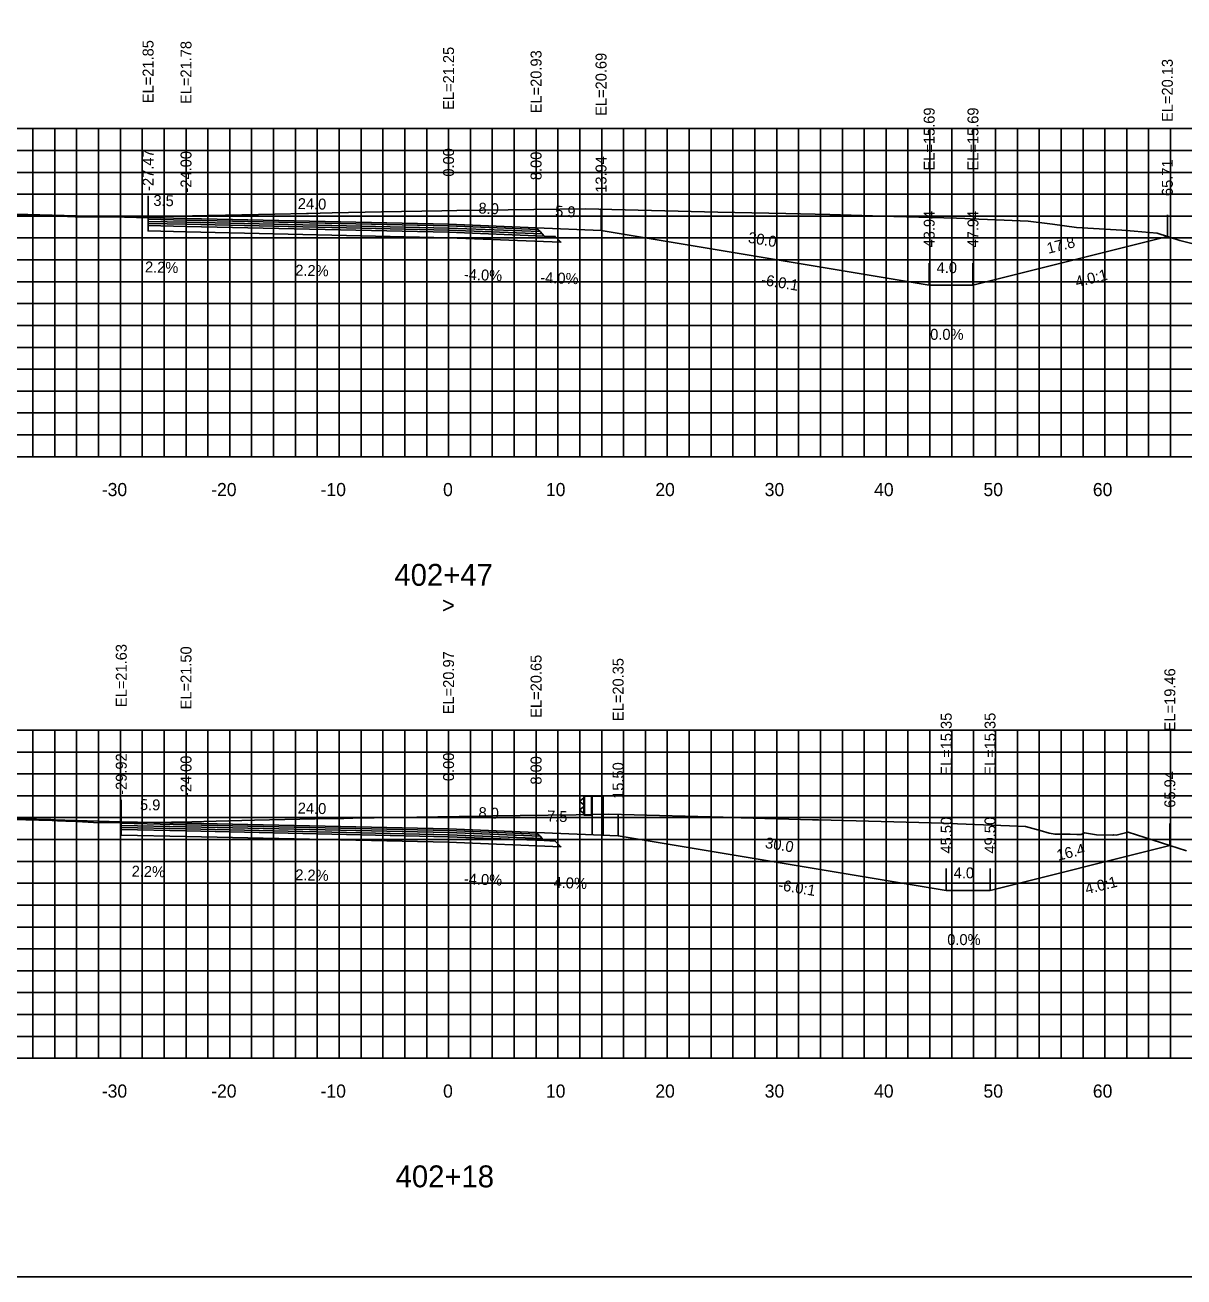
# Model space of a CAD drawing. Extents: x 1800976 to 1805104, y 250057 to 250580.
# Drawn here: x 1802252.3 to 1802358.2, y 250079.4 to 250193.9 of the extents above; entities that cross this region are included whole.
import ezdxf

# ---------------------------------------------------------------- set-up
doc = ezdxf.new("R2010")
doc.units = 0
for name, color, linetype in [('1', 7, 'Continuous'), ('10', 7, 'Continuous'), ('3', 7, 'Continuous'), ('4', 7, 'Continuous'), ('60', 7, 'Continuous'), ('BASE', 7, 'Continuous'), ('CL-CNST', 7, 'Continuous'), ('Level 1', 7, 'Continuous'), ('Level 62', 7, 'Continuous'), ('LOWER BINDER', 7, 'Continuous'), ('M-ROADS', 7, 'Continuous'), ('UPPER BINDER', 7, 'Continuous'), ('WEARING', 7, 'Continuous')]:
    doc.layers.add(name, color=color, linetype=linetype)

msp = doc.modelspace()

# ---------------------------------------------------------------- linework, layer by layer
for p, q in [((1802263.53, 250176.29), (1802263.53, 250178.29)), ((1802267, 250176.21), (1802267, 250178.21)), ((1802291, 250175.68), (1802291, 250177.68)), ((1802299, 250175.36), (1802299, 250177.36)), ((1802304.94, 250175.12), (1802304.94, 250177.12)), ((1802356.71, 250174.56), (1802356.71, 250176.56)), ((1802334.94, 250170.12), (1802334.94, 250172.12)), ((1802338.94, 250170.12), (1802338.94, 250172.12)), ((1802261.08, 250121.06), (1802261.08, 250123.06)), ((1802267, 250120.93), (1802267, 250122.93)), ((1802291, 250120.4), (1802291, 250122.4)), ((1802299, 250120.08), (1802299, 250122.08)), ((1802306.5, 250119.78), (1802306.5, 250121.78)), ((1802356.94, 250118.89), (1802356.94, 250120.89)), ((1802336.5, 250114.78), (1802336.5, 250116.78)), ((1802340.5, 250114.78), (1802340.5, 250116.78))]:
    msp.add_line(p, q)
msp.add_lwpolyline([(1802141, 250079.43), (1802441, 250079.43), (1802441, 250269.43), (1802141, 250269.43)], close=True)
at = {"layer": '60'}
for p, q in [((1802141, 250154.43), (1802441, 250154.43)), ((1802261, 250154.37), (1802261, 250154.43)), ((1802271, 250154.37), (1802271, 250154.43)), ((1802281, 250154.37), (1802281, 250154.43)), ((1802291, 250154.37), (1802291, 250154.43)), ((1802301, 250154.37), (1802301, 250154.43)), ((1802311, 250154.37), (1802311, 250154.43)), ((1802321, 250154.37), (1802321, 250154.43)), ((1802331, 250154.37), (1802331, 250154.43)), ((1802341, 250154.37), (1802341, 250154.43)), ((1802351, 250154.37), (1802351, 250154.43)), ((1802141, 250099.43), (1802441, 250099.43)), ((1802261, 250099.37), (1802261, 250099.43)), ((1802271, 250099.37), (1802271, 250099.43)), ((1802281, 250099.37), (1802281, 250099.43)), ((1802291, 250099.37), (1802291, 250099.43)), ((1802301, 250099.37), (1802301, 250099.43)), ((1802311, 250099.37), (1802311, 250099.43)), ((1802321, 250099.37), (1802321, 250099.43)), ((1802331, 250099.37), (1802331, 250099.43)), ((1802341, 250099.37), (1802341, 250099.43)), ((1802351, 250099.37), (1802351, 250099.43))]:
    msp.add_line(p, q, dxfattribs=at)
at = {"layer": 'BASE'}
for points in [[(1802263.53, 250175.57), (1802267, 250175.49), (1802291, 250174.96), (1802299.75, 250174.61), (1802300.75, 250174.57), (1802301.27, 250174.05), (1802291, 250174.46), (1802267, 250174.99), (1802263.53, 250175.07)], [(1802261.08, 250120.34), (1802267, 250120.21), (1802291, 250119.68), (1802299.75, 250119.33), (1802300.75, 250119.29), (1802301.27, 250118.77), (1802291, 250119.18), (1802267, 250119.71), (1802261.08, 250119.84)]]:
    msp.add_lwpolyline(points, close=True, dxfattribs=at)
at = {"layer": 'CL-CNST'}
for points in [[(1802251.44, 250176.61), (1802261.38, 250176.32), (1802263.53, 250176.27), (1802263.53, 250176.25)], [(1802263.53, 250176.29), (1802267, 250176.21), (1802291, 250175.68), (1802299, 250175.36), (1802304.94, 250175.12), (1802334.94, 250170.12), (1802338.94, 250170.12), (1802356.71, 250174.56)], [(1802242.86, 250121.52), (1802254.65, 250121.25), (1802254.93, 250121.24), (1802259.97, 250121.09), (1802261, 250121.06)], [(1802261.08, 250121.06), (1802267, 250120.93), (1802291, 250120.4), (1802299, 250120.08), (1802306.5, 250119.78), (1802336.5, 250114.78), (1802340.5, 250114.78), (1802356.94, 250118.89)]]:
    msp.add_lwpolyline(points, dxfattribs=at)
at = {"layer": 'Level 1'}
for p, q in [((1802303.38, 250123.25), (1802303.02, 250122.96)), ((1802303.38, 250123.4), (1802303.38, 250121.65)), ((1802305.13, 250123.4), (1802303.38, 250123.4)), ((1802303.43, 250123.4), (1802303.43, 250121.65)), ((1802304.08, 250123.4), (1802304.08, 250121.65)), ((1802304.13, 250123.4), (1802304.13, 250119.88)), ((1802305.13, 250123.4), (1802305.13, 250119.84)), ((1802303.02, 250122.88), (1802303.38, 250122.6)), ((1802303.38, 250122.46), (1802303.02, 250122.16)), ((1802303.02, 250122.09), (1802303.38, 250121.8)), ((1802304.13, 250121.65), (1802303.38, 250121.65))]:
    msp.add_line(p, q, dxfattribs=at)
for centre in [(1802303.05, 250122.92), (1802303.05, 250122.13)]:
    msp.add_arc(centre, 0.05, 135, 226.6208, dxfattribs=at)
at = {"layer": 'Level 62'}
for p, q in [((1802141, 250184.43), (1802441, 250184.43)), ((1802253, 250154.43), (1802253, 250184.43)), ((1802255, 250154.43), (1802255, 250184.43)), ((1802257, 250154.43), (1802257, 250184.43)), ((1802259, 250154.43), (1802259, 250184.43)), ((1802261, 250154.43), (1802261, 250184.43)), ((1802263, 250154.43), (1802263, 250184.43)), ((1802265, 250154.43), (1802265, 250184.43)), ((1802267, 250154.43), (1802267, 250184.43)), ((1802269, 250154.43), (1802269, 250184.43)), ((1802271, 250154.43), (1802271, 250184.43)), ((1802273, 250154.43), (1802273, 250184.43)), ((1802275, 250154.43), (1802275, 250184.43)), ((1802277, 250154.43), (1802277, 250184.43)), ((1802279, 250154.43), (1802279, 250184.43)), ((1802281, 250154.43), (1802281, 250184.43)), ((1802283, 250154.43), (1802283, 250184.43)), ((1802285, 250154.43), (1802285, 250184.43)), ((1802287, 250154.43), (1802287, 250184.43)), ((1802289, 250154.43), (1802289, 250184.43)), ((1802291, 250154.43), (1802291, 250184.43)), ((1802293, 250154.43), (1802293, 250184.43)), ((1802295, 250154.43), (1802295, 250184.43)), ((1802297, 250154.43), (1802297, 250184.43)), ((1802299, 250154.43), (1802299, 250184.43)), ((1802301, 250154.43), (1802301, 250184.43)), ((1802303, 250154.43), (1802303, 250184.43)), ((1802305, 250154.43), (1802305, 250184.43)), ((1802307, 250154.43), (1802307, 250184.43)), ((1802309, 250154.43), (1802309, 250184.43)), ((1802311, 250154.43), (1802311, 250184.43)), ((1802313, 250154.43), (1802313, 250184.43)), ((1802315, 250154.43), (1802315, 250184.43)), ((1802317, 250154.43), (1802317, 250184.43)), ((1802319, 250154.43), (1802319, 250184.43)), ((1802321, 250154.43), (1802321, 250184.43)), ((1802323, 250154.43), (1802323, 250184.43)), ((1802325, 250154.43), (1802325, 250184.43)), ((1802327, 250154.43), (1802327, 250184.43)), ((1802329, 250154.43), (1802329, 250184.43)), ((1802331, 250154.43), (1802331, 250184.43)), ((1802333, 250154.43), (1802333, 250184.43)), ((1802335, 250154.43), (1802335, 250184.43)), ((1802337, 250154.43), (1802337, 250184.43)), ((1802339, 250154.43), (1802339, 250184.43)), ((1802341, 250154.43), (1802341, 250184.43)), ((1802343, 250154.43), (1802343, 250184.43)), ((1802345, 250154.43), (1802345, 250184.43)), ((1802347, 250154.43), (1802347, 250184.43)), ((1802349, 250154.43), (1802349, 250184.43)), ((1802351, 250154.43), (1802351, 250184.43)), ((1802353, 250154.43), (1802353, 250184.43)), ((1802355, 250154.43), (1802355, 250184.43)), ((1802357, 250154.43), (1802357, 250184.43)), ((1802141, 250182.43), (1802441, 250182.43)), ((1802141, 250180.43), (1802441, 250180.43)), ((1802141, 250178.43), (1802441, 250178.43)), ((1802141, 250176.43), (1802441, 250176.43)), ((1802141, 250174.43), (1802441, 250174.43)), ((1802141, 250172.43), (1802441, 250172.43)), ((1802141, 250170.43), (1802441, 250170.43)), ((1802141, 250168.43), (1802441, 250168.43)), ((1802141, 250166.43), (1802441, 250166.43)), ((1802141, 250164.43), (1802441, 250164.43)), ((1802141, 250162.43), (1802441, 250162.43)), ((1802141, 250160.43), (1802441, 250160.43)), ((1802141, 250158.43), (1802441, 250158.43)), ((1802141, 250156.43), (1802441, 250156.43)), ((1802141, 250154.43), (1802441, 250154.43)), ((1802141, 250129.43), (1802441, 250129.43)), ((1802253, 250099.43), (1802253, 250129.43)), ((1802255, 250099.43), (1802255, 250129.43)), ((1802257, 250099.43), (1802257, 250129.43)), ((1802259, 250099.43), (1802259, 250129.43)), ((1802261, 250099.43), (1802261, 250129.43)), ((1802263, 250099.43), (1802263, 250129.43)), ((1802265, 250099.43), (1802265, 250129.43)), ((1802267, 250099.43), (1802267, 250129.43)), ((1802269, 250099.43), (1802269, 250129.43)), ((1802271, 250099.43), (1802271, 250129.43)), ((1802273, 250099.43), (1802273, 250129.43)), ((1802275, 250099.43), (1802275, 250129.43)), ((1802277, 250099.43), (1802277, 250129.43)), ((1802279, 250099.43), (1802279, 250129.43)), ((1802281, 250099.43), (1802281, 250129.43)), ((1802283, 250099.43), (1802283, 250129.43)), ((1802285, 250099.43), (1802285, 250129.43)), ((1802287, 250099.43), (1802287, 250129.43)), ((1802289, 250099.43), (1802289, 250129.43)), ((1802291, 250099.43), (1802291, 250129.43)), ((1802293, 250099.43), (1802293, 250129.43)), ((1802295, 250099.43), (1802295, 250129.43)), ((1802297, 250099.43), (1802297, 250129.43)), ((1802299, 250099.43), (1802299, 250129.43)), ((1802301, 250099.43), (1802301, 250129.43)), ((1802303, 250099.43), (1802303, 250129.43)), ((1802305, 250099.43), (1802305, 250129.43)), ((1802307, 250099.43), (1802307, 250129.43)), ((1802309, 250099.43), (1802309, 250129.43)), ((1802311, 250099.43), (1802311, 250129.43)), ((1802313, 250099.43), (1802313, 250129.43)), ((1802315, 250099.43), (1802315, 250129.43)), ((1802317, 250099.43), (1802317, 250129.43)), ((1802319, 250099.43), (1802319, 250129.43)), ((1802321, 250099.43), (1802321, 250129.43)), ((1802323, 250099.43), (1802323, 250129.43)), ((1802325, 250099.43), (1802325, 250129.43)), ((1802327, 250099.43), (1802327, 250129.43)), ((1802329, 250099.43), (1802329, 250129.43)), ((1802331, 250099.43), (1802331, 250129.43)), ((1802333, 250099.43), (1802333, 250129.43)), ((1802335, 250099.43), (1802335, 250129.43)), ((1802337, 250099.43), (1802337, 250129.43)), ((1802339, 250099.43), (1802339, 250129.43)), ((1802341, 250099.43), (1802341, 250129.43)), ((1802343, 250099.43), (1802343, 250129.43)), ((1802345, 250099.43), (1802345, 250129.43)), ((1802347, 250099.43), (1802347, 250129.43)), ((1802349, 250099.43), (1802349, 250129.43)), ((1802351, 250099.43), (1802351, 250129.43)), ((1802353, 250099.43), (1802353, 250129.43)), ((1802355, 250099.43), (1802355, 250129.43)), ((1802357, 250099.43), (1802357, 250129.43)), ((1802141, 250127.43), (1802441, 250127.43)), ((1802141, 250125.43), (1802441, 250125.43)), ((1802141, 250123.43), (1802441, 250123.43)), ((1802141, 250121.43), (1802441, 250121.43)), ((1802141, 250119.43), (1802441, 250119.43)), ((1802141, 250117.43), (1802441, 250117.43)), ((1802141, 250115.43), (1802441, 250115.43)), ((1802141, 250113.43), (1802441, 250113.43)), ((1802141, 250111.43), (1802441, 250111.43)), ((1802141, 250109.43), (1802441, 250109.43)), ((1802141, 250107.43), (1802441, 250107.43)), ((1802141, 250105.43), (1802441, 250105.43)), ((1802141, 250103.43), (1802441, 250103.43)), ((1802141, 250101.43), (1802441, 250101.43)), ((1802141, 250099.43), (1802441, 250099.43))]:
    msp.add_line(p, q, dxfattribs=at)
at = {"layer": 'LOWER BINDER'}
for points in [[(1802267, 250175.87), (1802291, 250175.34), (1802299.36, 250175.01), (1802299.55, 250174.81), (1802291, 250175.15), (1802267, 250175.68), (1802263.53, 250175.76), (1802263.53, 250175.95)], [(1802267, 250175.68), (1802291, 250175.15), (1802299.55, 250174.81), (1802299.75, 250174.61), (1802291, 250174.96), (1802267, 250175.49), (1802263.53, 250175.57), (1802263.53, 250175.76)], [(1802267, 250120.59), (1802291, 250120.06), (1802299.36, 250119.73), (1802299.55, 250119.53), (1802291, 250119.87), (1802267, 250120.4), (1802261.08, 250120.53), (1802261.08, 250120.72)], [(1802267, 250120.4), (1802291, 250119.87), (1802299.55, 250119.53), (1802299.75, 250119.33), (1802291, 250119.68), (1802267, 250120.21), (1802261.08, 250120.34), (1802261.08, 250120.53)]]:
    msp.add_lwpolyline(points, close=True, dxfattribs=at)
at = {"layer": 'M-ROADS'}
for points in [[(1802249.64, 250176.61), (1802252.58, 250176.54), (1802253.34, 250176.51), (1802253.83, 250176.49), (1802255.43, 250176.42), (1802256.86, 250176.36), (1802262.14, 250176.36), (1802263.94, 250176.37), (1802265.04, 250176.4), (1802267.58, 250176.47), (1802275.13, 250176.62), (1802278.01, 250176.68), (1802278.2, 250176.68), (1802279.26, 250176.71), (1802280.37, 250176.73), (1802284.88, 250176.81), (1802290.39, 250176.92), (1802291.75, 250176.95), (1802298.79, 250177.03), (1802303.53, 250177.1), (1802309.54, 250176.94), (1802315.62, 250176.79), (1802321.84, 250176.67), (1802325.85, 250176.59), (1802331.71, 250176.41), (1802337.43, 250176.24), (1802338.19, 250176.2), (1802338.68, 250176.18), (1802341.07, 250176.08), (1802343.98, 250175.97), (1802346.2, 250175.69), (1802348.4, 250175.4), (1802352.55, 250175.16), (1802353.67, 250175.05), (1802355.77, 250174.86), (1802357.86, 250174.2), (1802360.54, 250173.53)], [(1802249.89, 250121.29), (1802254.76, 250121.17), (1802255.26, 250121.15), (1802256.01, 250121.12), (1802257.05, 250121.07), (1802259.03, 250120.97), (1802265.68, 250121.01), (1802266.11, 250121.01), (1802266.39, 250121.02), (1802269.76, 250121.12), (1802273.25, 250121.2), (1802280.19, 250121.35), (1802280.32, 250121.35), (1802281.43, 250121.36), (1802282.25, 250121.38), (1802293.91, 250121.58), (1802294.98, 250121.6), (1802302.66, 250121.7), (1802305.65, 250121.74), (1802317.25, 250121.43), (1802317.76, 250121.41), (1802324.27, 250121.24), (1802324.76, 250121.23), (1802324.82, 250121.23), (1802336.29, 250120.91), (1802337.11, 250120.88), (1802337.54, 250120.86), (1802342.27, 250120.67), (1802343.73, 250120.61), (1802345.07, 250120.24), (1802345.9, 250120.01), (1802346.44, 250119.91), (1802347.82, 250119.91), (1802348.44, 250119.9), (1802348.82, 250119.89), (1802349.14, 250120.03), (1802350.22, 250119.86), (1802351.74, 250119.83), (1802351.8, 250119.85), (1802352.04, 250119.84), (1802353.12, 250120.11), (1802358.45, 250118.41)]]:
    msp.add_lwpolyline(points, dxfattribs=at)
at = {"layer": 'UPPER BINDER'}
for points in [[(1802299.36, 250175.01), (1802299.16, 250175.2), (1802291, 250175.53), (1802267, 250176.06), (1802263.53, 250176.14), (1802263.53, 250175.95), (1802267, 250175.87), (1802291, 250175.34)], [(1802299.36, 250119.73), (1802299.16, 250119.93), (1802291, 250120.25), (1802267, 250120.78), (1802261.08, 250120.91), (1802261.08, 250120.72), (1802267, 250120.59), (1802291, 250120.06)]]:
    msp.add_lwpolyline(points, close=True, dxfattribs=at)
at = {"layer": 'WEARING'}
for points in [[(1802299.16, 250175.2), (1802299, 250175.36), (1802291, 250175.68), (1802267, 250176.21), (1802263.53, 250176.29), (1802263.53, 250176.14), (1802267, 250176.06), (1802291, 250175.53)], [(1802299.16, 250119.93), (1802299, 250120.08), (1802291, 250120.4), (1802267, 250120.93), (1802261.08, 250121.06), (1802261.08, 250120.91), (1802267, 250120.78), (1802291, 250120.25)]]:
    msp.add_lwpolyline(points, close=True, dxfattribs=at)

# ---------------------------------------------------------------- texts
for s, rotation, p in [('4.0:1', 14.0362, (1802348.43, 250169.92)), ('-6.0:1', 350.5377, (1802319.53, 250170.16)), ('-6.0:1', 350.5377, (1802321.09, 250114.82)), ('4.0:1', 14.0362, (1802349.33, 250114.41))]:
    msp.add_text(s, height=1, rotation=rotation).set_placement(p)
at = {"layer": '1'}
for s, p in [('402+47', (1802286.05, 250142.63)), ('402+18', (1802286.16, 250087.63))]:
    msp.add_text(s, height=2, dxfattribs=at).set_placement(p)
at = {"layer": '10'}
for s, p in [('-30', (1802259.3, 250150.83)), ('-20', (1802269.3, 250150.83)), ('-10', (1802279.3, 250150.83)), ('0', (1802290.5, 250150.83)), ('10', (1802299.9, 250150.83)), ('20', (1802309.9, 250150.83)), ('30', (1802319.9, 250150.83)), ('40', (1802329.9, 250150.83)), ('50', (1802339.9, 250150.83)), ('60', (1802349.9, 250150.83)), ('-30', (1802259.3, 250095.83)), ('-20', (1802269.3, 250095.83)), ('-10', (1802279.3, 250095.83)), ('0', (1802290.5, 250095.83)), ('10', (1802299.9, 250095.83)), ('20', (1802309.9, 250095.83)), ('30', (1802319.9, 250095.83)), ('40', (1802329.9, 250095.83)), ('50', (1802339.9, 250095.83)), ('60', (1802349.9, 250095.83))]:
    msp.add_text(s, height=1.2, dxfattribs=at).set_placement(p)
at = {"layer": '3'}
for s, p in [('EL=21.85', (1802264.03, 250186.76)), ('EL=21.78', (1802267.5, 250186.68)), ('EL=21.25', (1802291.5, 250186.15)), ('EL=20.93', (1802299.5, 250185.83)), ('EL=20.69', (1802305.44, 250185.6)), ('EL=20.13', (1802357.21, 250185.04)), ('EL=15.69', (1802335.44, 250180.6)), ('EL=15.69', (1802339.44, 250180.6)), ('0.00', (1802291.5, 250180.04)), ('-27.47', (1802264.03, 250178.74)), ('-24.00', (1802267.5, 250178.59)), ('8.00', (1802299.5, 250179.72)), ('13.94', (1802305.44, 250178.57)), ('65.71', (1802357.21, 250178.27)), ('43.94', (1802335.44, 250173.57)), ('47.94', (1802339.44, 250173.57)), ('EL=21.63', (1802261.58, 250131.54)), ('EL=21.50', (1802267.5, 250131.33)), ('EL=20.97', (1802291.5, 250130.88)), ('EL=20.65', (1802299.5, 250130.56)), ('EL=20.35', (1802307, 250130.26)), ('EL=19.46', (1802357.44, 250129.32)), ('EL=15.35', (1802337, 250125.26)), ('EL=15.35', (1802341, 250125.26)), ('-29.92', (1802261.58, 250123.52)), ('-24.00', (1802267.5, 250123.31)), ('0.00', (1802291.5, 250124.77)), ('8.00', (1802299.5, 250124.45)), ('15.50', (1802307, 250123.15)), ('65.94', (1802357.44, 250122.34)), ('45.50', (1802337, 250118.15)), ('49.50', (1802341, 250118.15))]:
    msp.add_text(s, height=1, rotation=90, dxfattribs=at).set_placement(p)
at = {"layer": '4'}
for s, rotation, p in [('3.5', 358.7397, (1802264.01, 250177.37)), ('24.0', 358.7397, (1802277.21, 250177.08)), ('8.0', 357.7094, (1802293.72, 250176.67)), ('5.9', 357.7094, (1802300.73, 250176.39)), ('30.0', 350.5377, (1802318.33, 250174.01)), ('17.8', 14.0362, (1802345.83, 250172.98)), ('2.2%', 358.7397, (1802263.24, 250171.29)), ('2.2%', 358.7397, (1802276.98, 250170.99)), ('-4.0%', 357.7094, (1802292.39, 250170.62)), ('-4.0%', 357.7094, (1802299.37, 250170.34)), ('5.9', 358.7397, (1802262.78, 250122.13)), ('24.0', 358.7397, (1802277.21, 250121.81)), ('8.0', 357.7094, (1802293.72, 250121.4)), ('7.5', 357.7094, (1802299.99, 250121.09)), ('30.0', 350.5377, (1802319.89, 250118.67)), ('16.4', 14.0362, (1802346.73, 250117.48)), ('2.2%', 358.7397, (1802262.02, 250116.04)), ('2.2%', 358.7397, (1802276.98, 250115.71)), ('-4.0%', 357.7094, (1802292.39, 250115.35)), ('-4.0%', 357.7094, (1802300.14, 250115.04))]:
    msp.add_text(s, height=1, rotation=rotation, dxfattribs=at).set_placement(p)
for s, p in [('4.0', (1802335.62, 250171.22)), ('0.0%', (1802335.03, 250165.12)), ('4.0', (1802337.18, 250115.88)), ('0.0%', (1802336.59, 250109.78))]:
    msp.add_text(s, height=1, dxfattribs=at).set_placement(p)
at = {"layer": '60'}
msp.add_text('>', height=1.5, dxfattribs=at).set_placement((1802290.39, 250140.11))

doc.saveas('drawing.dxf')
